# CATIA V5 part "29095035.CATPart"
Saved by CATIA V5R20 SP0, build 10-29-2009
Part number: 29095035
Definition: NONE
Nomenclature: 29095035
Source: Unknown
Description: 29095035
Bounding box of the stored display mesh (mm): x -17.5 to 44.548, y -61.5 to 96.048, z -51.5 to 51.5
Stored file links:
  C:\Users\Utente\Desktop\IO LAVORO\3D X SITO CF\X SITO\PLASTICA\RF1\29095035.CATPart
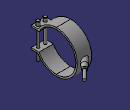
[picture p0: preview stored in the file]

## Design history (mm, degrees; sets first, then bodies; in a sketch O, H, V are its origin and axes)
Body1 "29095035" (main body)
  Solid1: solid without history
